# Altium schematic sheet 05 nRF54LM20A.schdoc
size 400 x 277 mm; Device: default420x297; Symbol: default420x297; Name: default420x297; Size: "A3"; Id: /; File: 05 nRF54LM20A; Sheet: /
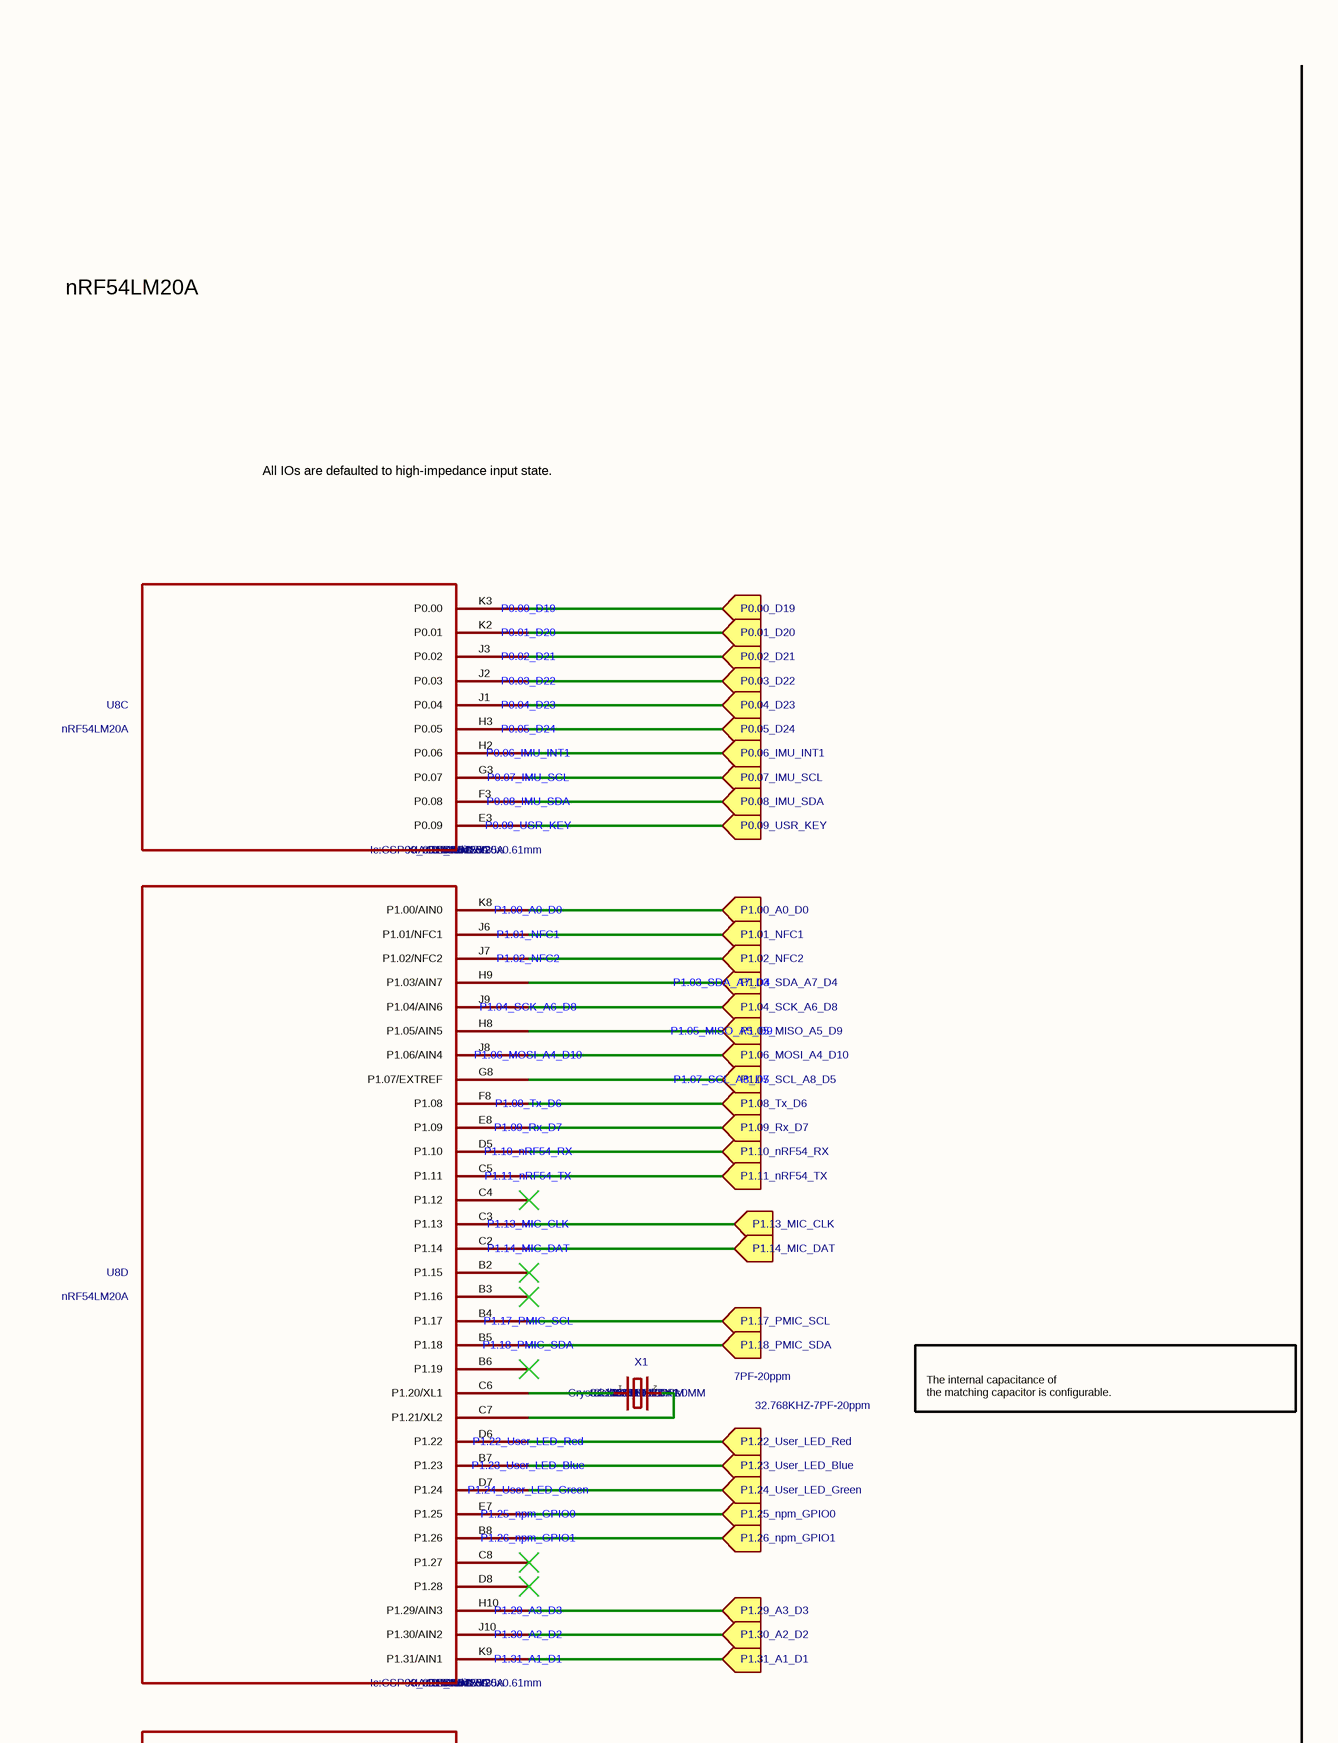
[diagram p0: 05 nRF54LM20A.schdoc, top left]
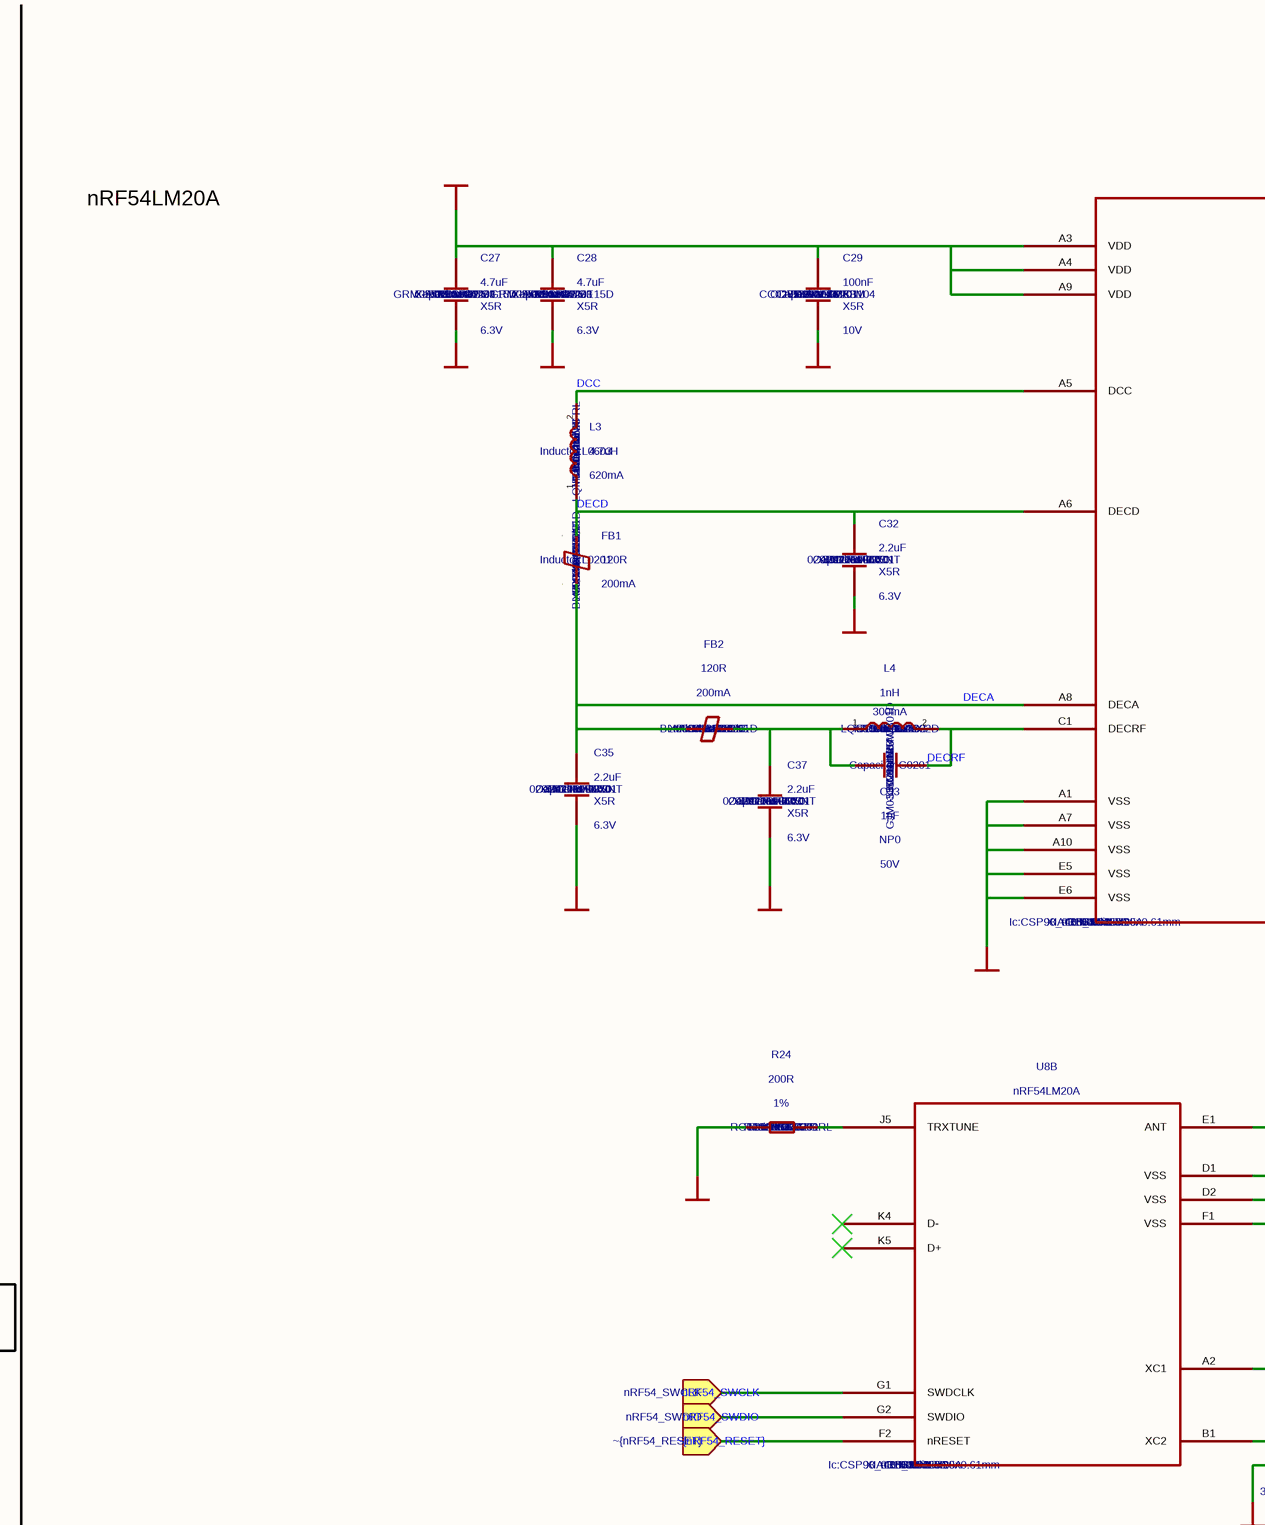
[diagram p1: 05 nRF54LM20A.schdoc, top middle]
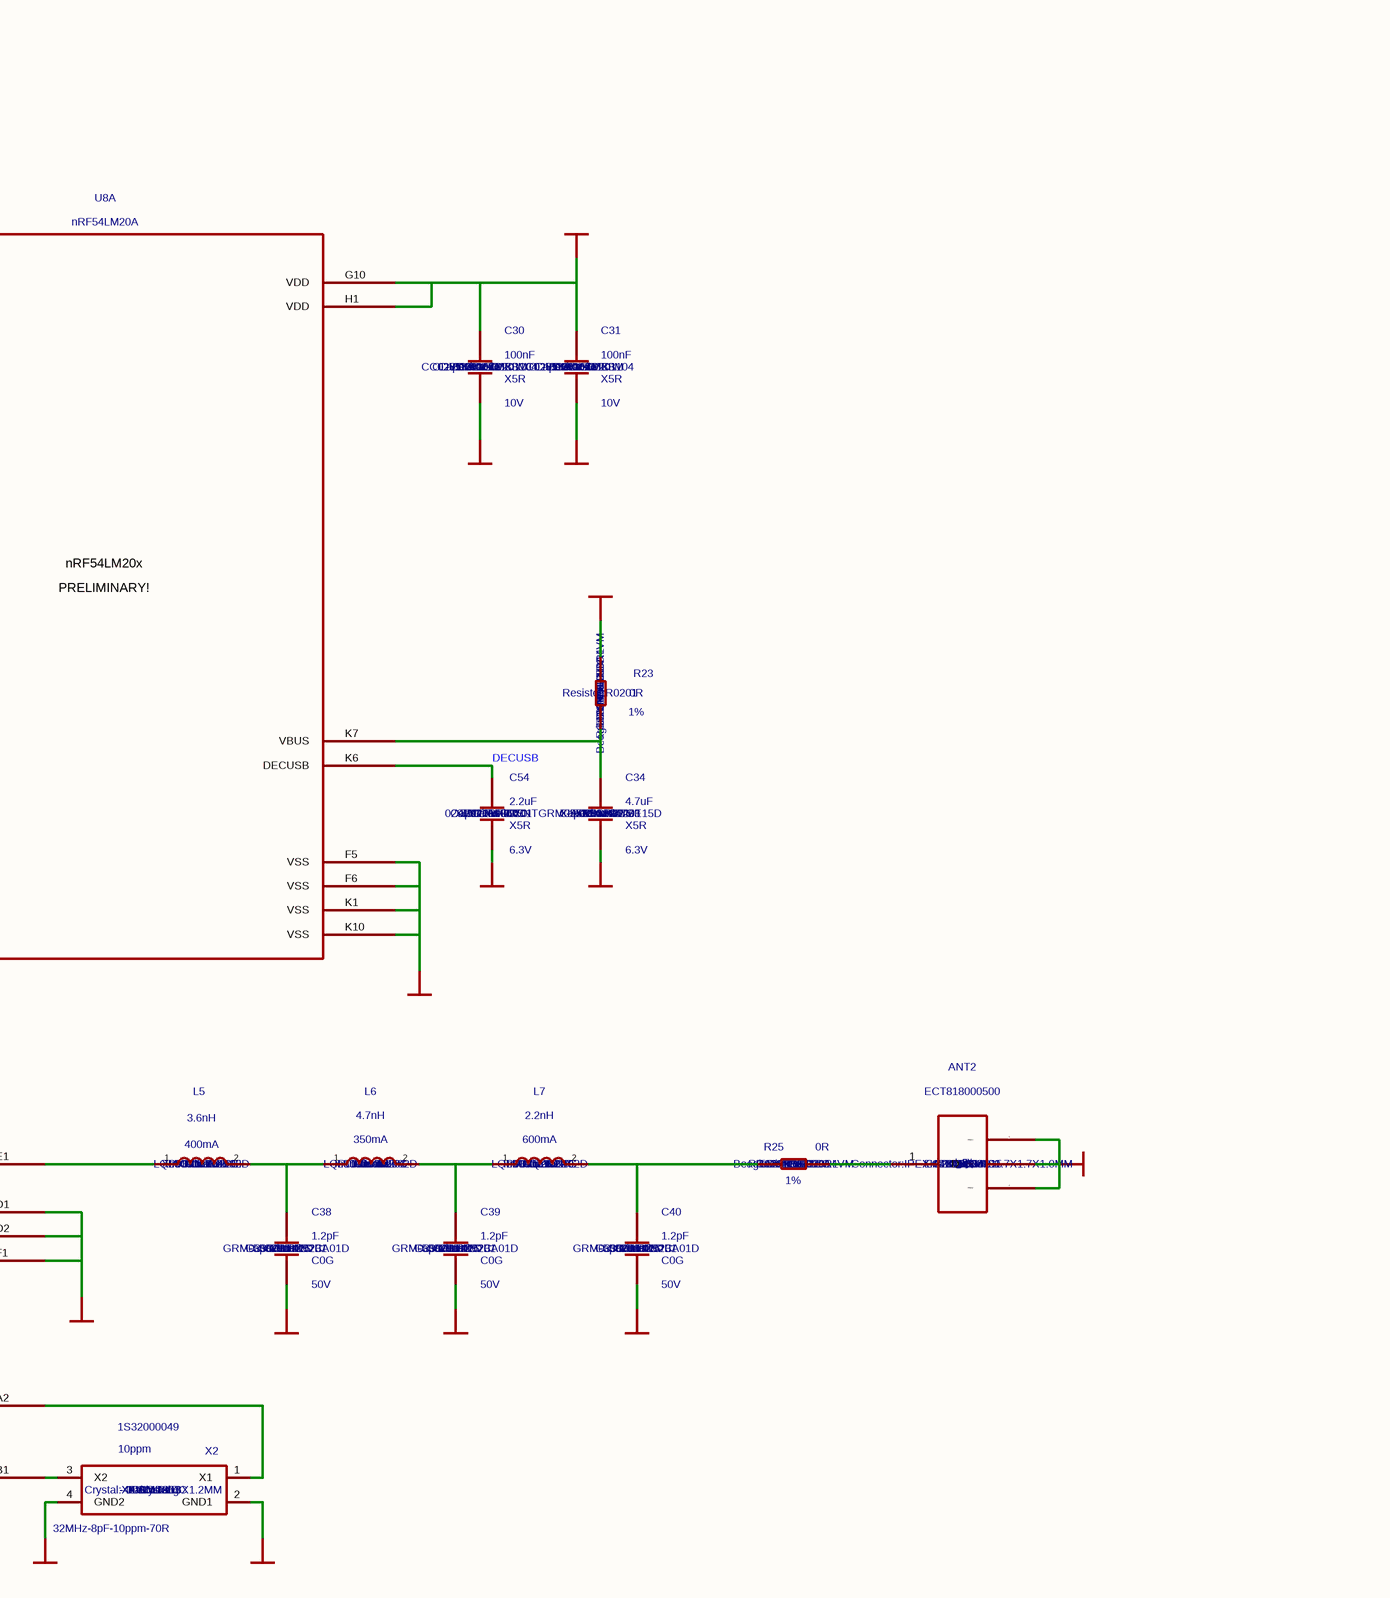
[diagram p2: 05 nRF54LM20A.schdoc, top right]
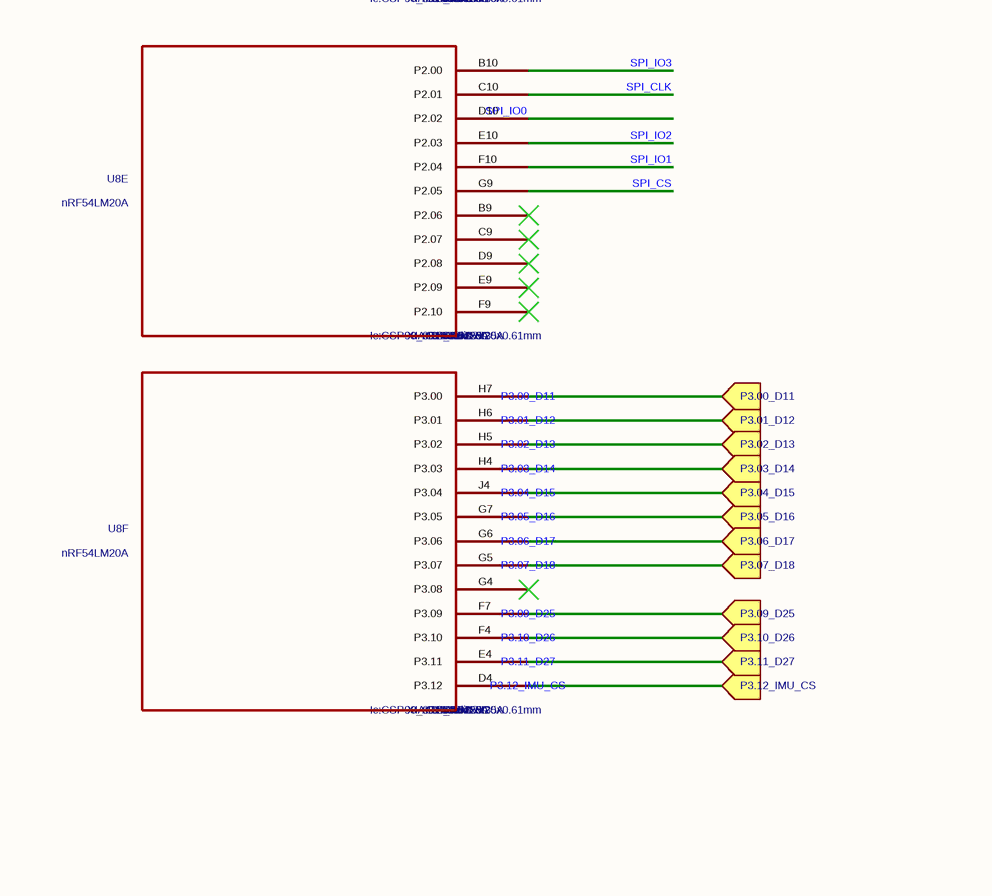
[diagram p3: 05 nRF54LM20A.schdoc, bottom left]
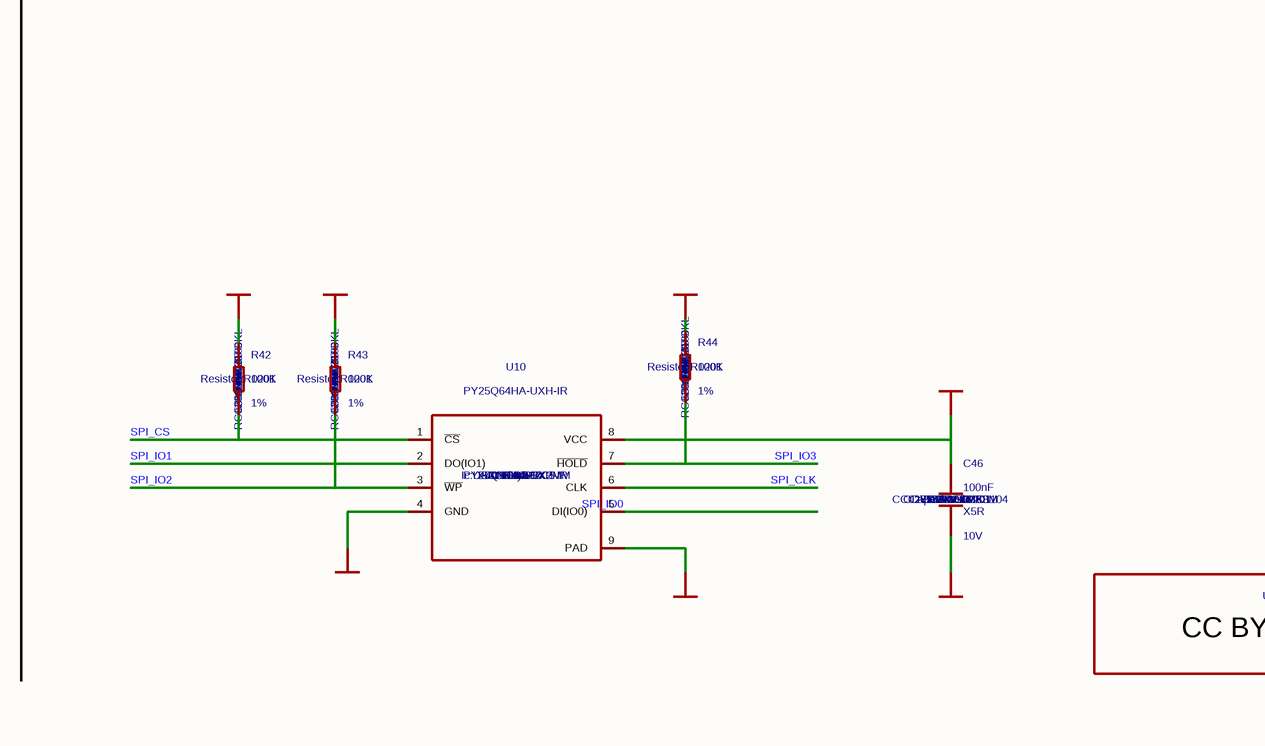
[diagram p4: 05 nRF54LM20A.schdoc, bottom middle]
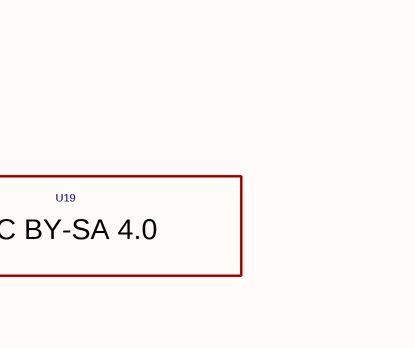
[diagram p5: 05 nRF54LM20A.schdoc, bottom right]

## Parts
ANT2  value ECT818000500  Manufacturer: 电联  SKU: 320080244  Part Type: Connector  Status: XIAO nRF54L15  Temperature: -40°C to 85°C  [Connector:IPEX-GEN4-SMD-1.7X1.7X1.0MM]  (hidden comment: Seeed_libdb_Connector/CN400ECT81-QE7VTN)
C27  value 4.7uF  Manufacturer: Murata  MPN: GRM035R60J475ME15D  SKU: 302013247  Dielectric: X5R  Part Type: Ceramic  Voltage Rating: 6.3V  Status: XIAO ESP32 S3  Temperature: -55°C to 85°C  [Capacitor:C0201]  (hidden comment: Seeed_libdb_Capacitors/CA20147UF0-SN7236)
C28  value 4.7uF  Manufacturer: Murata  MPN: GRM035R60J475ME15D  SKU: 302013247  Dielectric: X5R  Part Type: Ceramic  Voltage Rating: 6.3V  Status: XIAO ESP32 S3  Temperature: -55°C to 85°C  [Capacitor:C0201]  (hidden comment: Seeed_libdb_Capacitors/CA20147UF0-SN7236)
C29  value 100nF  Manufacturer: YAGEO  MPN: CC0201KRX5R6BB104  SKU: 302010271  Dielectric: X5R  Part Type: Ceramic  Voltage Rating: 10V  Status: ODYSSEY-i.MX8M  Temperature: -55°C to 85°C  [Capacitor:C0201]  (hidden comment: Seeed_libdb_Capacitors/CA201100NF-SQS4XQ)
C30  value 100nF  Manufacturer: YAGEO  MPN: CC0201KRX5R6BB104  SKU: 302010271  Dielectric: X5R  Part Type: Ceramic  Voltage Rating: 10V  Status: ODYSSEY-i.MX8M  Temperature: -55°C to 85°C  [Capacitor:C0201]  (hidden comment: Seeed_libdb_Capacitors/CA201100NF-SQS4XQ)
C31  value 100nF  Manufacturer: YAGEO  MPN: CC0201KRX5R6BB104  SKU: 302010271  Dielectric: X5R  Part Type: Ceramic  Voltage Rating: 10V  Status: ODYSSEY-i.MX8M  Temperature: -55°C to 85°C  [Capacitor:C0201]  (hidden comment: Seeed_libdb_Capacitors/CA201100NF-SQS4XQ)
C32  value 2.2uF  Manufacturer: FH  MPN: 0201X225M6R3NT  SKU: 302012960  Dielectric: X5R  Part Type: Ceramic  Voltage Rating: 6.3V  Status: XIAO_RP2350  Temperature: -55°C to 85°C  [Capacitor:C0201]  (hidden comment: Seeed_libdb_Capacitors/CA20122UF0-RZ5XFV)
C33  value 1pF  Manufacturer: Murata  MPN: GJM0335C1H1R0WB01D  SKU: 302011834  Dielectric: NP0  Part Type: Ceramic  Voltage Rating: 50V  Temperature: -55°C to 125°C  [Capacitor:C0201]  (hidden comment: Seeed_libdb_Capacitors/CA2011PF00-VNS767)
C34  value 4.7uF  Manufacturer: Murata  MPN: GRM035R60J475ME15D  SKU: 302013247  Dielectric: X5R  Part Type: Ceramic  Voltage Rating: 6.3V  Status: XIAO ESP32 S3  Temperature: -55°C to 85°C  [Capacitor:C0201]  (hidden comment: Seeed_libdb_Capacitors/CA20147UF0-SN7236)
C35  value 2.2uF  Manufacturer: FH  MPN: 0201X225M6R3NT  SKU: 302012960  Dielectric: X5R  Part Type: Ceramic  Voltage Rating: 6.3V  Status: XIAO_RP2350  Temperature: -55°C to 85°C  [Capacitor:C0201]  (hidden comment: Seeed_libdb_Capacitors/CA20122UF0-RZ5XFV)
C37  value 2.2uF  Manufacturer: FH  MPN: 0201X225M6R3NT  SKU: 302012960  Dielectric: X5R  Part Type: Ceramic  Voltage Rating: 6.3V  Status: XIAO_RP2350  Temperature: -55°C to 85°C  [Capacitor:C0201]  (hidden comment: Seeed_libdb_Capacitors/CA20122UF0-RZ5XFV)
C38  value 1.2pF  Manufacturer: Murata  MPN: GRM0335C1H1R2BA01D  SKU: 302013750  Dielectric: C0G  Part Type: Ceramic  Voltage Rating: 50V  Status: ZBT-2  Temperature: -55°C to 125°C  [Capacitor:C0201]  (hidden comment: Seeed_libdb_Capacitors/CA20112PF0-2QK9VB)
C39  value 1.2pF  Manufacturer: Murata  MPN: GRM0335C1H1R2BA01D  SKU: 302013750  Dielectric: C0G  Part Type: Ceramic  Voltage Rating: 50V  Status: ZBT-2  Temperature: -55°C to 125°C  [Capacitor:C0201]  (hidden comment: Seeed_libdb_Capacitors/CA20112PF0-2QK9VB)
C40  value 1.2pF  Manufacturer: Murata  MPN: GRM0335C1H1R2BA01D  SKU: 302013750  Dielectric: C0G  Part Type: Ceramic  Voltage Rating: 50V  Status: ZBT-2  Temperature: -55°C to 125°C  [Capacitor:C0201]  (hidden comment: Seeed_libdb_Capacitors/CA20112PF0-2QK9VB)
C46  value 100nF  Manufacturer: YAGEO  MPN: CC0201KRX5R6BB104  SKU: 302010271  Dielectric: X5R  Part Type: Ceramic  Voltage Rating: 10V  Status: ODYSSEY-i.MX8M  Temperature: -55°C to 85°C  [Capacitor:C0201]  (hidden comment: Seeed_libdb_Capacitors/CA201100NF-SQS4XQ)
C54  value 2.2uF  Manufacturer: FH  MPN: 0201X225M6R3NT  SKU: 302012960  Dielectric: X5R  Part Type: Ceramic  Voltage Rating: 6.3V  Status: XIAO_RP2350  Temperature: -55°C to 85°C  [Capacitor:C0201]  (hidden comment: Seeed_libdb_Capacitors/CA20122UF0-RZ5XFV)
FB1  value 120R  Manufacturer: Murata  MPN: BLM03AG121SN1D  SKU: 303030259  Part Type: Ferrite Bead  Rating: 200mA  Status: XIAO nRF54L15  Temperature: -55°C to 125°C  [Inductor:L0201]  (hidden comment: Seeed_libdb_Ferrite Bead/FB201120R0-7K43FG)
FB2  value 120R  Manufacturer: Murata  MPN: BLM03AG121SN1D  SKU: 303030259  Part Type: Ferrite Bead  Rating: 200mA  Status: XIAO nRF54L15  Temperature: -55°C to 125°C  [Inductor:L0201]  (hidden comment: Seeed_libdb_Ferrite Bead/FB201120R0-7K43FG)
L3  value 4.7uH  Manufacturer: Murata  MPN: LQM18PN4R7MFRL  SKU: 303011912  Part Type: Inductor  Rating: 620mA  Status: Frame 2 EVT  Temperature: -40°C to 85°C  [Inductor:L0603]  (hidden comment: Seeed_libdb_Inductor/IN60347UH0-3HHEBJ)
L4  value 1nH  Manufacturer: Murata  MPN: LQG15HN1N0S02D  SKU: 303011145  Part Type: Inductor  Rating: 300mA  Status: Jetson Nano  Temperature: -55°C to 125°C  [Inductor:L0402]  (hidden comment: Seeed_libdb_Inductor/IN4021NH00-AAH8QL)
L5  value 3.6nH  Manufacturer: Murata  MPN: LQP03TN3N6B02D  SKU: 303011721  Part Type: Inductor  Rating: 400mA  Status: XIAO nRF54L15  Temperature: -55°C to 125°C  [Inductor:L0201]  (hidden comment: Seeed_libdb_Inductor/IN20136NH0-JK535W)
L6  value 4.7nH  Manufacturer: Murata  MPN: LQP03TN4N7J02D  SKU: 303010096  Part Type: Inductor  Rating: 350mA  Status: Friends  Temperature: -55°C to 125°C  [Inductor:L0201]  (hidden comment: Seeed_libdb_Inductor/IN20147NH0-5A5TSK)
L7  value 2.2nH  Manufacturer: Murata  MPN: LQP03TQ2N2B02D  SKU: 303011229  Part Type: Inductor  Rating: 600mA  Status: HA Voice KIT  Temperature: -55°C to 125°C  [Inductor:L0201]  (hidden comment: Seeed_libdb_Inductor/IN20122NH0-5UJVAZ)
R23  value 0R  Manufacturer: YAGEO  MPN: RC0201FR-070RL  SKU: 301010525  Tolerance: 1%  Part Type: RES  Status: BeagleBone AI TDA4VM  Temperature: -55°C to 125°C  [Resistor:R0201]  (hidden comment: Seeed_libdb_Resistors/RE2010R000-2FV3F9)
R24  value 200R  Manufacturer: YAGEO  MPN: RC0201FR-07200RL  SKU: 301013351  Tolerance: 1%  Part Type: RES  Status: Frame 2 EVT  Temperature: -55°C to 155°C  [Resistor:R0201]  (hidden comment: Seeed_libdb_Resistors/RE201200R0-LEQHKJ)
R25  value 0R  Manufacturer: YAGEO  MPN: RC0201FR-070RL  SKU: 301010525  Tolerance: 1%  Part Type: RES  Status: BeagleBone AI TDA4VM  Temperature: -55°C to 125°C  [Resistor:R0201]  (hidden comment: Seeed_libdb_Resistors/RE2010R000-2FV3F9)
R42  value 100K  Manufacturer: YAGEO  MPN: RC0201FR-07100KL  SKU: 301010765  Tolerance: 1%  Part Type: RES  Status: XIAO  Temperature: -55°C to 125°C  [Resistor:R0201]  (hidden comment: Seeed_libdb_Resistors/RE201100K0-XFHWYX)
R43  value 100K  Manufacturer: YAGEO  MPN: RC0201FR-07100KL  SKU: 301010765  Tolerance: 1%  Part Type: RES  Status: XIAO  Temperature: -55°C to 125°C  [Resistor:R0201]  (hidden comment: Seeed_libdb_Resistors/RE201100K0-XFHWYX)
R44  value 100K  Manufacturer: YAGEO  MPN: RC0201FR-07100KL  SKU: 301010765  Tolerance: 1%  Part Type: RES  Status: XIAO  Temperature: -55°C to 125°C  [Resistor:R0201]  (hidden comment: Seeed_libdb_Resistors/RE201100K0-XFHWYX)
U8  value nRF54LM20A  Manufacturer: Nordic  SKU: 310000155  Part Type: IC  Status: XIAO nRF54LM20A  Temperature: -40°C to 85°C  [Ic:CSP98_0.35_3.67x3.85x0.61mm]  (hidden comment: Seeed_libdb_Ic/IC980NRF54-QTPAQA)  (parts A,B,C,D,E,F of 6)
U10  value PY25Q64HA-UXH-IR  Manufacturer: Puya  SKU: 310000014  Part Type: Flash  Status: XIAO ESP32C5  Temperature: -40°C to 85°C  Priority: A  [Ic:USON8-0.5-3X2MM]  (hidden comment: Seeed_libdb_Ic/IC800PY25Q-8RKSKZ)
U19  Misc_LOGO_CC_BY-SA_4.0  [Misc:LOGO_CC_BY-SA_4.0]  (value not drawn)
X1  value 32.768KHZ-7PF-20ppm  Manufacturer: Seiko Instruments  MPN: SC16S-7PF20PPM  SKU: 306010970  Part Type: Crystal  Rating: 7PF-20ppm  Status: XIAO BLE  [Crystal:X2-SMD-1.6X1.0MM]  (hidden comment: Seeed_libdb_OSC & XTAL/OS20032768-6DZQLS)
X2  value 32MHz-8pF-10ppm-70R  Manufacturer: Faith Long  MPN: 1S32000049  SKU: 306011503  Part Type: Crystal  Rating: 10ppm  Status: XIAO BLE  Temperature: -40°C to 85°C  [Crystal:X4-SMD-1.6X1.2MM]  (hidden comment: Seeed_libdb_OSC & XTAL/OS40032MHZ-GQ8NAJ)

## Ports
nRF54_SWCLK (in), nRF54_SWDIO (in), P0.00_D19 (in), P0.01_D20 (in), P0.02_D21 (in), P0.03_D22 (in), P0.04_D23 (in), P0.05_D24 (in), P0.06_IMU_INT1 (in), P0.07_IMU_SCL (in), P0.08_IMU_SDA (in), P0.09_USR_KEY (in), P1.00_A0_D0 (in), P1.01_NFC1 (in), P1.02_NFC2 (in), P1.03_SDA_A7_D4 (in), P1.04_SCK_A6_D8 (in), P1.05_MISO_A5_D9 (in), P1.06_MOSI_A4_D10 (in), P1.07_SCL_A8_D5 (in), P1.08_Tx_D6 (in), P1.09_Rx_D7 (in), P1.10_nRF54_RX (in), P1.11_nRF54_TX (in), P1.13_MIC_CLK (in), P1.14_MIC_DAT (in), P1.17_PMIC_SCL (in), P1.18_PMIC_SDA (in), P1.22_User_LED_Red (in), P1.23_User_LED_Blue (in), P1.24_User_LED_Green (in), P1.25_npm_GPIO0 (in), P1.26_npm_GPIO1 (in), P1.29_A3_D3 (in), P1.30_A2_D2 (in), P1.31_A1_D1 (in), P3.00_D11 (in), P3.01_D12 (in), P3.02_D13 (in), P3.03_D14 (in), P3.04_D15 (in), P3.05_D16 (in), P3.06_D17 (in), P3.07_D18 (in), P3.09_D25 (in), P3.10_D26 (in), P3.11_D27 (in), P3.12_IMU_CS (in), ~{nRF54_RESET} (in)

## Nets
power_+5V: C27.1 C28.1 C29.1 C30.1 C31.1 C46.1 R23.2 R42.2 R43.2 R44.2 U8.A3(VDD) U8.A4(VDD) U8.A9(VDD) U8.G10(VDD) U8.H1(VDD) U10.8(VCC)
Power_Gnd_GNDREF: ANT2.2(GND1) ANT2.3(GND1) ANT2.4(GND2) C27.2 C28.2 C29.2 C30.2 C31.2 C32.2 C34.2 C35.2 C37.2 C38.2 C39.2 C40.2 C46.2 C54.2 R24.1 U8.A1(VSS) U8.A7(VSS) U8.A10(VSS) U8.D1(VSS) U8.D2(VSS) U8.E5(VSS) U8.E6(VSS) U8.F1(VSS) U8.F5(VSS) U8.F6(VSS) U8.K1(VSS) U8.K10(VSS) U10.4(GND) U10.9(PAD) X2.2(GND1) X2.4(GND2)
DCC: L3.2 U8.A5(DCC)
DECA: C35.1 FB1.1 FB2.2 U8.A8(DECA)
DECD: C32.1 FB1.2 L3.1 U8.A6(DECD)
DECRF: C33.1 L4.2 U8.C1(DECRF)
DECUSB: C54.1 U8.K6(DECUSB)
nRF54_SWCLK: U8.G1(SWDCLK) ; port nRF54_SWCLK
nRF54_SWDIO: U8.G2(SWDIO) ; port nRF54_SWDIO
P0.00_D19: U8.K3(P0.00) ; port P0.00_D19
P0.01_D20: U8.K2(P0.01) ; port P0.01_D20
P0.02_D21: U8.J3(P0.02) ; port P0.02_D21
P0.03_D22: U8.J2(P0.03) ; port P0.03_D22
P0.04_D23: U8.J1(P0.04) ; port P0.04_D23
P0.05_D24: U8.H3(P0.05) ; port P0.05_D24
P0.06_IMU_INT1: U8.H2(P0.06) ; port P0.06_IMU_INT1
P0.07_IMU_SCL: U8.G3(P0.07) ; port P0.07_IMU_SCL
P0.08_IMU_SDA: U8.F3(P0.08) ; port P0.08_IMU_SDA
P0.09_USR_KEY: U8.E3(P0.09) ; port P0.09_USR_KEY
P1.00_A0_D0: U8.K8(P1.00/AIN0) ; port P1.00_A0_D0
P1.01_NFC1: U8.J6(P1.01/NFC1) ; port P1.01_NFC1
P1.02_NFC2: U8.J7(P1.02/NFC2) ; port P1.02_NFC2
P1.03_SDA_A7_D4: U8.H9(P1.03/AIN7) ; port P1.03_SDA_A7_D4
P1.04_SCK_A6_D8: U8.J9(P1.04/AIN6) ; port P1.04_SCK_A6_D8
P1.05_MISO_A5_D9: U8.H8(P1.05/AIN5) ; port P1.05_MISO_A5_D9
P1.06_MOSI_A4_D10: U8.J8(P1.06/AIN4) ; port P1.06_MOSI_A4_D10
P1.07_SCL_A8_D5: U8.G8(P1.07/EXTREF) ; port P1.07_SCL_A8_D5
P1.08_Tx_D6: U8.F8(P1.08) ; port P1.08_Tx_D6
P1.09_Rx_D7: U8.E8(P1.09) ; port P1.09_Rx_D7
P1.10_nRF54_RX: U8.D5(P1.10) ; port P1.10_nRF54_RX
P1.11_nRF54_TX: U8.C5(P1.11) ; port P1.11_nRF54_TX
P1.13_MIC_CLK: U8.C3(P1.13) ; port P1.13_MIC_CLK
P1.14_MIC_DAT: U8.C2(P1.14) ; port P1.14_MIC_DAT
P1.17_PMIC_SCL: U8.B4(P1.17) ; port P1.17_PMIC_SCL
P1.18_PMIC_SDA: U8.B5(P1.18) ; port P1.18_PMIC_SDA
P1.22_User_LED_Red: U8.D6(P1.22) ; port P1.22_User_LED_Red
P1.23_User_LED_Blue: U8.B7(P1.23) ; port P1.23_User_LED_Blue
P1.24_User_LED_Green: U8.D7(P1.24) ; port P1.24_User_LED_Green
P1.25_npm_GPIO0: U8.E7(P1.25) ; port P1.25_npm_GPIO0
P1.26_npm_GPIO1: U8.B8(P1.26) ; port P1.26_npm_GPIO1
P1.29_A3_D3: U8.H10(P1.29/AIN3) ; port P1.29_A3_D3
P1.30_A2_D2: U8.J10(P1.30/AIN2) ; port P1.30_A2_D2
P1.31_A1_D1: U8.K9(P1.31/AIN1) ; port P1.31_A1_D1
P3.00_D11: U8.H7(P3.00) ; port P3.00_D11
P3.01_D12: U8.H6(P3.01) ; port P3.01_D12
P3.02_D13: U8.H5(P3.02) ; port P3.02_D13
P3.03_D14: U8.H4(P3.03) ; port P3.03_D14
P3.04_D15: U8.J4(P3.04) ; port P3.04_D15
P3.05_D16: U8.G7(P3.05) ; port P3.05_D16
P3.06_D17: U8.G6(P3.06) ; port P3.06_D17
P3.07_D18: U8.G5(P3.07) ; port P3.07_D18
P3.09_D25: U8.F7(P3.09) ; port P3.09_D25
P3.10_D26: U8.F4(P3.10) ; port P3.10_D26
P3.11_D27: U8.E4(P3.11) ; port P3.11_D27
P3.12_IMU_CS: U8.D4(P3.12) ; port P3.12_IMU_CS
SPI_CLK: U8.C10(P2.01) U10.6(CLK)
SPI_CS: R42.1 U8.G9(P2.05) U10.1(~{CS})
SPI_IO0: U8.D10(P2.02) U10.5(DI(IO0))
SPI_IO1: U8.F10(P2.04) U10.2(DO(IO1))
SPI_IO2: R43.1 U8.E10(P2.03) U10.3(~{WP})
SPI_IO3: R44.1 U8.B10(P2.00) U10.7(~{HOLD})
~{nRF54_RESET}: U8.F2(nRESET) ; port ~{nRF54_RESET}
NetANT2_1: ANT2.1(D) R25.2
NetC33_2: C33.2 C37.1 FB2.1 L4.1
NetC34_1: C34.1 R23.1 U8.K7(VBUS)
NetC38_1: C38.1 L5.2 L6.1
NetC39_1: C39.1 L6.2 L7.1
NetC40_1: C40.1 L7.2 R25.1
NetL5_1: L5.1 U8.E1(ANT)
NetR24_2: R24.2 U8.J5(TRXTUNE)
NetU8_A2: U8.A2(XC1) X2.1(X1)
NetU8_B1: U8.B1(XC2) X2.3(X2)
NetU8_C6: U8.C6(P1.20/XL1) X1.1
NetU8_C7: U8.C7(P1.21/XL2) X1.2

Not connected (* = marked no-connect by the designer): U8 B2(P1.15)* B3(P1.16)* B6(P1.19)* B9(P2.06)* C4(P1.12)* C8(P1.27)* C9(P2.07)* D8(P1.28)* D9(P2.08)* E9(P2.09)* F9(P2.10)* G4(P3.08)* K4(D-)* K5(D+)*

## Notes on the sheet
- nRF54LM20A
- All IOs are defaulted to high-impedance input state.
- The internal capacitance of
  the matching capacitor is configurable.

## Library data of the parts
ANT2 = Seeed_libdb_Connector/CN400ECT81-QE7VTN: SMD IPEX-GEN4 Female CONN;4P-L1.7*W1.7*H0.6mm; UniqueId: 8d88eafcc5a7cade; AddInBom: yes
C27 = Seeed_libdb_Capacitors/CA20147UF0-SN7236: SMD CAP Ceramic 4.7uF-6.3V-20%-X5R;0201; UniqueId: a26eb100929f0697; AddInBom: yes
C28 = Seeed_libdb_Capacitors/CA20147UF0-SN7236: SMD CAP Ceramic 4.7uF-6.3V-20%-X5R;0201; UniqueId: e3aeb17489c0ab5d; AddInBom: yes
C29 = Seeed_libdb_Capacitors/CA201100NF-SQS4XQ: SMD CAP Ceramic 100nF-10V-10%-X5R;0201; UniqueId: 5bfcee5f0e3d202c; AddInBom: yes
C30 = Seeed_libdb_Capacitors/CA201100NF-SQS4XQ: SMD CAP Ceramic 100nF-10V-10%-X5R;0201; UniqueId: a2ee6ceb65d30336; AddInBom: yes
C31 = Seeed_libdb_Capacitors/CA201100NF-SQS4XQ: SMD CAP Ceramic 100nF-10V-10%-X5R;0201; UniqueId: cc1d00c51cc12124; AddInBom: yes
C32 = Seeed_libdb_Capacitors/CA20122UF0-RZ5XFV: SMD CAP Ceramic 2.2uF-6.3V-20%-X5R;0201; UniqueId: d2625f4b4bd439ef; AddInBom: yes
C33 = Seeed_libdb_Capacitors/CA2011PF00-VNS767: SMD CAP Ceramic 1PF-50V-0.05pF-C0G/NP0;0201; UniqueId: deb55bbe20a101cf; AddInBom: yes
C34 = Seeed_libdb_Capacitors/CA20147UF0-SN7236: SMD CAP Ceramic 4.7uF-6.3V-20%-X5R;0201; UniqueId: 553def7d7947fca6; AddInBom: yes
C35 = Seeed_libdb_Capacitors/CA20122UF0-RZ5XFV: SMD CAP Ceramic 2.2uF-6.3V-20%-X5R;0201; UniqueId: 2b4e6e580c7acde0; AddInBom: yes
C37 = Seeed_libdb_Capacitors/CA20122UF0-RZ5XFV: SMD CAP Ceramic 2.2uF-6.3V-20%-X5R;0201; UniqueId: ff078052695da6b6; AddInBom: yes
C38 = Seeed_libdb_Capacitors/CA20112PF0-2QK9VB: SMD CAP Ceramic 1.2pF±0.1pF-50V-C0G;0201; UniqueId: 6827ca7a6bd67e26; AddInBom: yes
C39 = Seeed_libdb_Capacitors/CA20112PF0-2QK9VB: SMD CAP Ceramic 1.2pF±0.1pF-50V-C0G;0201; UniqueId: 54d3d224326b3f8f; AddInBom: yes
C40 = Seeed_libdb_Capacitors/CA20112PF0-2QK9VB: SMD CAP Ceramic 1.2pF±0.1pF-50V-C0G;0201; UniqueId: 12af2948e5a85261; AddInBom: yes
C46 = Seeed_libdb_Capacitors/CA201100NF-SQS4XQ: SMD CAP Ceramic 100nF-10V-10%-X5R;0201; UniqueId: df918f74c5ced612; AddInBom: yes
C54 = Seeed_libdb_Capacitors/CA20122UF0-RZ5XFV: SMD CAP Ceramic 2.2uF-6.3V-20%-X5R;0201; UniqueId: 65328433fb04ddb7; AddInBom: yes
FB1 = Seeed_libdb_Ferrite Bead/FB201120R0-7K43FG: SMD Ferrite Bead 120R-200mA;0201; UniqueId: 323bb55b4674cf0d; AddInBom: yes
FB2 = Seeed_libdb_Ferrite Bead/FB201120R0-7K43FG: SMD Ferrite Bead 120R-200mA;0201; UniqueId: 62384c8cdaa0e7c8; AddInBom: yes
L3 = Seeed_libdb_Inductor/IN60347UH0-3HHEBJ: SMD Inductor 4.7uH-20%-620mA;0603; UniqueId: 510f7e7047da8839; AddInBom: yes
L4 = Seeed_libdb_Inductor/IN4021NH00-AAH8QL: SMD Inductor 1nH-0.3nH-300mA;0402; UniqueId: fd5a5c0f77d1aabb; AddInBom: yes
L5 = Seeed_libdb_Inductor/IN20136NH0-JK535W: SMD Inductor;3.6nH-0.1H-400mA;0201; UniqueId: a672ad5603fb0b7d; AddInBom: yes
L6 = Seeed_libdb_Inductor/IN20147NH0-5A5TSK: SMD Inductor;4.7nH-5%-350mA;0201; UniqueId: 47af25b8573c8ed0; AddInBom: yes
L7 = Seeed_libdb_Inductor/IN20122NH0-5UJVAZ: SMD Inductor 2.2nH-0.1nH-650mA;0201; UniqueId: 6645345e349bedbf; AddInBom: yes
R23 = Seeed_libdb_Resistors/RE2010R000-2FV3F9: SMD RES 0R-±1%-1/20W;0201; UniqueId: d92c635076b33213; AddInBom: yes
R24 = Seeed_libdb_Resistors/RE201200R0-LEQHKJ: SMD RES 200R-1%-1/20W;0201; UniqueId: f7952e9f9cd6773b; AddInBom: yes
R25 = Seeed_libdb_Resistors/RE2010R000-2FV3F9: SMD RES 0R-±1%-1/20W;0201; UniqueId: 6f4c4beafd605d3e; AddInBom: yes
R42 = Seeed_libdb_Resistors/RE201100K0-XFHWYX: SMD RES 100K-±1%-1/20W;0201; UniqueId: 3520350cb8a16ddf; AddInBom: yes
R43 = Seeed_libdb_Resistors/RE201100K0-XFHWYX: SMD RES 100K-±1%-1/20W;0201; UniqueId: 1ad54b734ffff27e; AddInBom: yes
R44 = Seeed_libdb_Resistors/RE201100K0-XFHWYX: SMD RES 100K-±1%-1/20W;0201; UniqueId: 3f1747bc7cd0165c; AddInBom: yes
U8 = Seeed_libdb_Ic/IC980NRF54-QTPAQA: SMD IC;CSP98_3.9x3.7mm;; UniqueId: 484e3008dca2bfa8; AddInBom: yes
U10 = Seeed_libdb_Ic/IC800PY25Q-8RKSKZ: SMD IC Memory;QSPI Ultra Low Power Flash;64Mb;USON8 3*2*0.55mm; UniqueId: c69de7c088414df5; AddInBom: yes
U19 = Misc_LOGO_CC_BY-SA_4.0: UniqueId: a4a6b0395ae03088; AddInBom: yes
X1 = Seeed_libdb_OSC & XTAL/OS20032768-6DZQLS: SMD Crystal 32.768KHZ-7PF-20ppm;2p-1.6*1.0*0.5mm; UniqueId: 220c9828e5ec91fa; AddInBom: yes
X2 = Seeed_libdb_OSC & XTAL/OS40032MHZ-GQ8NAJ: SMD Crystal 32MHz-8pF-10ppm-70R;4P-L1.6*W1.2*H0.35mm; UniqueId: bfe3f639d49cbe8f; AddInBom: yes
